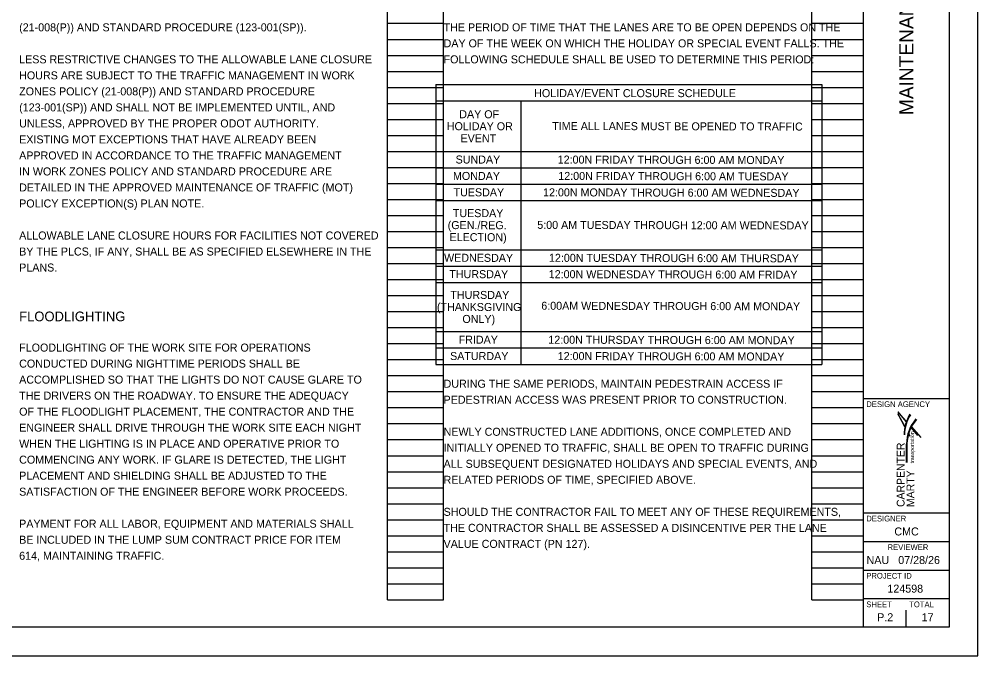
# Model space of a CAD drawing. Extents: x 0 to 34, y 0 to 22.
# Drawn here: x 17.24 to 34, y 0 to 11.13 of the extents above; entities that cross this region are included whole.
import ezdxf

# ---------------------------------------------------------------- set-up
doc = ezdxf.new("R2010")
doc.units = 0
for name, color, linetype in [('SH_Border', 7, 'Continuous'), ('SH_Cut_Line', 7, 'Continuous'), ('SH_Data', 7, 'Continuous'), ('SH_Text', 7, 'Continuous')]:
    doc.layers.add(name, color=color, linetype=linetype)

msp = doc.modelspace()

# ---------------------------------------------------------------- linework, layer by layer
at = {"layer": 'SH_Border'}
for p, q in [((32, 0.5), (32, 21.5)), ((32, 4.5), (33.5, 4.5)), ((32, 2.5), (33.5, 2.5)), ((32, 2), (33.5, 2)), ((32, 1.5), (33.5, 1.5)), ((32, 1), (33.5, 1))]:
    msp.add_line(p, q, dxfattribs=at)
msp.add_lwpolyline([(1.5, 21.5), (33.5, 21.5), (33.5, 0.5), (1.5, 0.5)], close=True, dxfattribs=at)
at = {"layer": 'SH_Cut_Line'}
msp.add_lwpolyline([(0, 0), (34, 0), (34, 22), (0, 22)], close=True, dxfattribs=at)
at = {"layer": 'SH_Data'}
for p, q in [((23.68, 0.98), (23.68, 21.14)), ((24.66, 0.98), (24.66, 21.14)), ((31.1, 0.98), (31.1, 21.14)), ((32, 0.98), (32, 21.14)), ((23.68, 11.06), (24.66, 11.06)), ((31.1, 11.06), (32, 11.06)), ((23.68, 10.78), (24.66, 10.78)), ((31.1, 10.78), (32, 10.78)), ((23.68, 10.5), (24.66, 10.5)), ((31.1, 10.5), (32, 10.5)), ((23.68, 10.22), (24.66, 10.22)), ((31.1, 10.22), (32, 10.22)), ((23.68, 9.94), (24.66, 9.94)), ((31.1, 9.94), (32, 9.94)), ((23.68, 9.66), (24.66, 9.66)), ((31.1, 9.66), (32, 9.66)), ((23.68, 9.38), (24.66, 9.38)), ((31.1, 9.38), (32, 9.38)), ((23.68, 9.1), (24.66, 9.1)), ((31.1, 9.1), (32, 9.1)), ((23.68, 8.82), (24.66, 8.82)), ((31.1, 8.82), (32, 8.82)), ((23.68, 8.54), (24.66, 8.54)), ((31.1, 8.54), (32, 8.54)), ((23.68, 8.26), (24.66, 8.26)), ((31.1, 8.26), (32, 8.26)), ((23.68, 7.98), (24.66, 7.98)), ((31.1, 7.98), (32, 7.98)), ((23.68, 7.7), (24.66, 7.7)), ((31.1, 7.7), (32, 7.7)), ((23.68, 7.42), (24.66, 7.42)), ((31.1, 7.42), (32, 7.42)), ((23.68, 7.14), (24.66, 7.14)), ((31.1, 7.14), (32, 7.14)), ((23.68, 6.86), (24.66, 6.86)), ((31.1, 6.86), (32, 6.86)), ((23.68, 6.58), (24.66, 6.58)), ((31.1, 6.58), (32, 6.58)), ((23.68, 6.3), (24.66, 6.3)), ((31.1, 6.3), (32, 6.3)), ((23.68, 6.02), (24.66, 6.02)), ((31.1, 6.02), (32, 6.02)), ((23.68, 5.74), (24.66, 5.74)), ((31.1, 5.74), (32, 5.74)), ((23.68, 5.46), (24.66, 5.46)), ((31.1, 5.46), (32, 5.46)), ((23.68, 5.18), (24.66, 5.18)), ((31.1, 5.18), (32, 5.18)), ((23.68, 4.9), (24.66, 4.9)), ((31.1, 4.9), (32, 4.9)), ((23.68, 4.62), (24.66, 4.62)), ((31.1, 4.62), (32, 4.62)), ((23.68, 4.34), (24.66, 4.34)), ((31.1, 4.34), (32, 4.34)), ((23.68, 4.06), (24.66, 4.06)), ((31.1, 4.06), (32, 4.06)), ((23.68, 3.78), (24.66, 3.78)), ((31.1, 3.78), (32, 3.78)), ((23.68, 3.5), (24.66, 3.5)), ((31.1, 3.5), (32, 3.5)), ((32.75, 3.5), (32.75, 3.5)), ((23.68, 3.22), (24.66, 3.22)), ((31.1, 3.22), (32, 3.22)), ((23.68, 2.94), (24.66, 2.94)), ((31.1, 2.94), (32, 2.94)), ((23.68, 2.66), (24.66, 2.66)), ((31.1, 2.66), (32, 2.66)), ((23.68, 2.38), (24.66, 2.38)), ((31.1, 2.38), (32, 2.38)), ((23.68, 2.1), (24.66, 2.1)), ((31.1, 2.1), (32, 2.1)), ((23.68, 1.82), (24.66, 1.82)), ((31.1, 1.82), (32, 1.82)), ((23.68, 1.54), (24.66, 1.54)), ((31.1, 1.54), (32, 1.54)), ((23.68, 1.26), (24.66, 1.26)), ((31.1, 1.26), (32, 1.26)), ((23.68, 0.98), (24.66, 0.98)), ((31.1, 0.98), (32, 0.98)), ((32.375, 0.675), (32.375, 0.675)), ((32.75, 0.5), (32.75, 0.8))]:
    msp.add_line(p, q, dxfattribs=at)
at = {"layer": 'SH_Text'}
for p, q in [((24.522, 9.99), (24.522, 5.097)), ((24.522, 9.99), (31.274, 9.99)), ((31.274, 9.99), (31.274, 5.097)), ((24.522, 9.703), (31.274, 9.703)), ((26.009, 9.703), (26.009, 5.097)), ((24.522, 8.819), (31.274, 8.819)), ((24.522, 8.533), (31.274, 8.533)), ((24.522, 8.246), (31.274, 8.246)), ((24.522, 7.96), (31.274, 7.96)), ((24.522, 7.101), (31.274, 7.101)), ((24.522, 6.815), (31.274, 6.815)), ((24.522, 6.528), (31.274, 6.528)), ((24.522, 5.669), (31.274, 5.669)), ((24.522, 5.383), (31.274, 5.383)), ((24.522, 5.097), (31.274, 5.097)), ((32.721, 4.016), (32.602, 4.232)), ((32.811, 3.84), (32.79, 3.88)), ((32.82, 3.834), (32.791, 3.886)), ((32.952, 3.853), (32.834, 3.991)), ((32.839, 4.002), (33.006, 3.816)), ((32.755, 3.378), (32.755, 3.704)), ((32.762, 3.378), (32.762, 3.704))]:
    msp.add_line(p, q, dxfattribs=at)
for points in [[(32.746, 4.104), (32.601, 4.266)], [(32.601, 4.266), (32.744, 4.098)], [(32.721, 4.016), (32.602, 4.232)], [(32.602, 4.232), (32.719, 4.011)]]:
    msp.add_lwpolyline(points, dxfattribs=at)
for centre, radius, start, end in [((33.432, 3.86), 0.721, 149.5704, 179.5529), ((33.373, 3.862), 0.654, 147.1423, 179.6525), ((33.426, 3.704), 0.671, 139.2898, 180.0106), ((33.433, 3.688), 0.672, 138.5126, 178.6075)]:
    msp.add_arc(centre, radius, start, end, dxfattribs=at)

# ---------------------------------------------------------------- texts
at = {"layer": 'SH_Data'}
msp.add_text('MAINTENANCE OF TRAFFIC GENERAL NOTES', height=0.25, rotation=90, dxfattribs=at).set_placement((32.875, 9.455))
for s, height, p in [('DESIGN AGENCY', 0.1, (32.05, 4.35)), ('DESIGNER', 0.1, (32.05, 2.35)), ('CMC', 0.14, (32.541, 2.105)), ('REVIEWER', 0.1, (32.422, 1.85)), ('NAU', 0.14, (32.055, 1.605)), ('07/28/26', 0.14, (32.609, 1.605)), ('PROJECT ID', 0.1, (32.05, 1.35)), ('124598', 0.14, (32.419, 1.105)), ('SHEET', 0.1, (32.05, 0.85)), ('TOTAL', 0.1, (32.8, 0.85)), ('P.2', 0.14, (32.24, 0.605)), ('17', 0.14, (33.018, 0.605))]:
    msp.add_text(s, height=height, dxfattribs=at).set_placement(p)
at = {"layer": 'SH_Text'}
for s, height, p in [('(21-008(P)) AND STANDARD PROCEDURE (123-001(SP)).', 0.14, (17.24, 10.92)), ('THE PERIOD OF TIME THAT THE LANES ARE TO BE OPEN DEPENDS ON THE ', 0.14, (24.66, 10.92)), ('DAY OF THE WEEK ON WHICH THE HOLIDAY OR SPECIAL EVENT FALLS. THE ', 0.14, (24.66, 10.64)), ('LESS RESTRICTIVE CHANGES TO THE ALLOWABLE LANE CLOSURE', 0.14, (17.24, 10.36)), ('FOLLOWING SCHEDULE SHALL BE USED TO DETERMINE THIS PERIOD:', 0.14, (24.66, 10.36)), ('HOURS ARE SUBJECT TO THE TRAFFIC MANAGEMENT IN WORK', 0.14, (17.24, 10.08)), ('ZONES POLICY (21-008(P)) AND STANDARD PROCEDURE', 0.14, (17.24, 9.8)), ('HOLIDAY/EVENT CLOSURE SCHEDULE', 0.14, (26.244, 9.769)), ('(123-001(SP)) AND SHALL NOT BE IMPLEMENTED UNTIL, AND', 0.14, (17.24, 9.52)), ('UNLESS, APPROVED BY THE PROPER ODOT AUTHORITY.', 0.14, (17.24, 9.24)), ('EXISTING MOT EXCEPTIONS THAT HAVE ALREADY BEEN', 0.14, (17.24, 8.96)), ('APPROVED IN ACCORDANCE TO THE TRAFFIC MANAGEMENT', 0.14, (17.24, 8.68)), ('IN WORK ZONES POLICY AND STANDARD PROCEDURE ARE', 0.14, (17.24, 8.4)), ('DETAILED IN THE APPROVED MAINTENANCE OF TRAFFIC (MOT)', 0.14, (17.24, 8.12)), ('POLICY EXCEPTION(S) PLAN NOTE.', 0.14, (17.24, 7.84)), ('ALLOWABLE LANE CLOSURE HOURS FOR FACILITIES NOT COVERED', 0.14, (17.24, 7.28)), ('BY THE PLCS, IF ANY, SHALL BE AS SPECIFIED ELSEWHERE IN THE', 0.14, (17.24, 7)), ('PLANS.', 0.14, (17.24, 6.72)), ('FLOODLIGHTING', 0.17, (17.24, 5.85)), ('FLOODLIGHTING OF THE WORK SITE FOR OPERATIONS', 0.14, (17.24, 5.32)), ('CONDUCTED DURING NIGHTTIME PERIODS SHALL BE', 0.14, (17.24, 5.04)), ('ACCOMPLISHED SO THAT THE LIGHTS DO NOT CAUSE GLARE TO', 0.14, (17.24, 4.76)), ('DURING THE SAME PERIODS, MAINTAIN PEDESTRAIN ACCESS IF', 0.14, (24.66, 4.688)), ('THE DRIVERS ON THE ROADWAY. TO ENSURE THE ADEQUACY', 0.14, (17.24, 4.48)), ('PEDESTRIAN ACCESS WAS PRESENT PRIOR TO CONSTRUCTION.', 0.14, (24.66, 4.408)), ('OF THE FLOODLIGHT PLACEMENT, THE CONTRACTOR AND THE', 0.14, (17.24, 4.2)), ('ENGINEER SHALL DRIVE THROUGH THE WORK SITE EACH NIGHT', 0.14, (17.24, 3.92)), ('NEWLY CONSTRUCTED LANE ADDITIONS, ONCE COMPLETED AND', 0.14, (24.66, 3.848)), ('WHEN THE LIGHTING IS IN PLACE AND OPERATIVE PRIOR TO', 0.14, (17.24, 3.64)), ('INITIALLY OPENED TO TRAFFIC, SHALL BE OPEN TO TRAFFIC DURING', 0.14, (24.66, 3.568)), ('COMMENCING ANY WORK. IF GLARE IS DETECTED, THE LIGHT', 0.14, (17.24, 3.36)), ('ALL SUBSEQUENT DESIGNATED HOLIDAYS AND SPECIAL EVENTS, AND', 0.14, (24.66, 3.288)), ('PLACEMENT AND SHIELDING SHALL BE ADJUSTED TO THE', 0.14, (17.24, 3.08)), ('RELATED PERIODS OF TIME, SPECIFIED ABOVE.', 0.14, (24.66, 3.008)), ('SATISFACTION OF THE ENGINEER BEFORE WORK PROCEEDS.', 0.14, (17.24, 2.8)), ('SHOULD THE CONTRACTOR FAIL TO MEET ANY OF THESE REQUIREMENTS,', 0.14, (24.66, 2.448)), ('PAYMENT FOR ALL LABOR, EQUIPMENT AND MATERIALS SHALL', 0.14, (17.24, 2.24)), ('THE CONTRACTOR SHALL BE ASSESSED A DISINCENTIVE PER THE LANE', 0.14, (24.66, 2.168)), ('BE INCLUDED IN THE LUMP SUM CONTRACT PRICE FOR ITEM', 0.14, (17.24, 1.96)), ('VALUE CONTRACT (PN 127).', 0.14, (24.66, 1.888)), ('614, MAINTAINING TRAFFIC.', 0.14, (17.24, 1.68))]:
    msp.add_text(s, height=height, dxfattribs=at).set_placement(p)
for s, height, rotation, p in [('DAY OF ', 0.14, 359.8697, (24.934, 9.401)), ('HOLIDAY OR ', 0.14, 359.8697, (24.716, 9.192)), ('TIME ALL LANES MUST BE OPENED TO TRAFFIC', 0.14, 359.8697, (26.559, 9.195)), ('EVENT', 0.14, 359.8697, (24.956, 8.981)), ('SUNDAY', 0.14, 359.8697, (24.87, 8.609)), ('12:00N FRIDAY THROUGH 6:00 AM MONDAY', 0.14, 359.8697, (26.655, 8.608)), ('MONDAY', 0.14, 359.8697, (24.824, 8.322)), ('12:00N FRIDAY THROUGH 6:00 AM TUESDAY', 0.14, 359.8697, (26.665, 8.322)), ('TUESDAY', 0.14, 359.8697, (24.834, 8.036)), ('12:00N MONDAY THROUGH 6:00 AM WEDNESDAY', 0.14, 359.8697, (26.399, 8.035)), ('TUESDAY', 0.14, 359.8697, (24.821, 7.672)), ('(GEN./REG. ', 0.14, 359.8697, (24.732, 7.462)), ('5:00 AM TUESDAY THROUGH 12:00 AM WEDNESDAY', 0.14, 359.8697, (26.298, 7.466)), ('ELECTION)', 0.14, 359.8697, (24.764, 7.252)), ('WEDNESDAY', 0.14, 359.8697, (24.668, 6.891)), ('12:00N TUESDAY THROUGH 6:00 AM THURSDAY', 0.14, 359.8697, (26.502, 6.89)), ('THURSDAY', 0.14, 359.8697, (24.76, 6.605)), ('12:00N WEDNESDAY THROUGH 6:00 AM FRIDAY', 0.14, 359.8697, (26.498, 6.604)), ('THURSDAY ', 0.14, 359.8697, (24.778, 6.242)), ('(THANKSGIVING ', 0.14, 359.8697, (24.544, 6.032)), ('6:00AM WEDNESDAY THROUGH 6:00 AM MONDAY', 0.14, 359.8697, (26.368, 6.052)), ('ONLY)', 0.14, 359.8697, (24.989, 5.821)), ('FRIDAY', 0.14, 359.8697, (24.923, 5.459)), ('12:00N THURSDAY THROUGH 6:00 AM MONDAY', 0.14, 359.8697, (26.491, 5.458)), ('SATURDAY', 0.14, 359.8697, (24.773, 5.173)), ('12:00N FRIDAY THROUGH 6:00 AM MONDAY', 0.14, 359.8697, (26.655, 5.172)), ('transportation', 0.06649, 90, (32.885, 3.364)), ('CARPENTER ', 0.1367, 90, (32.719, 2.602)), ('MARTY', 0.1367, 90, (32.891, 2.602))]:
    msp.add_text(s, height=height, rotation=rotation, dxfattribs=at).set_placement(p)

doc.saveas('drawing.dxf')
